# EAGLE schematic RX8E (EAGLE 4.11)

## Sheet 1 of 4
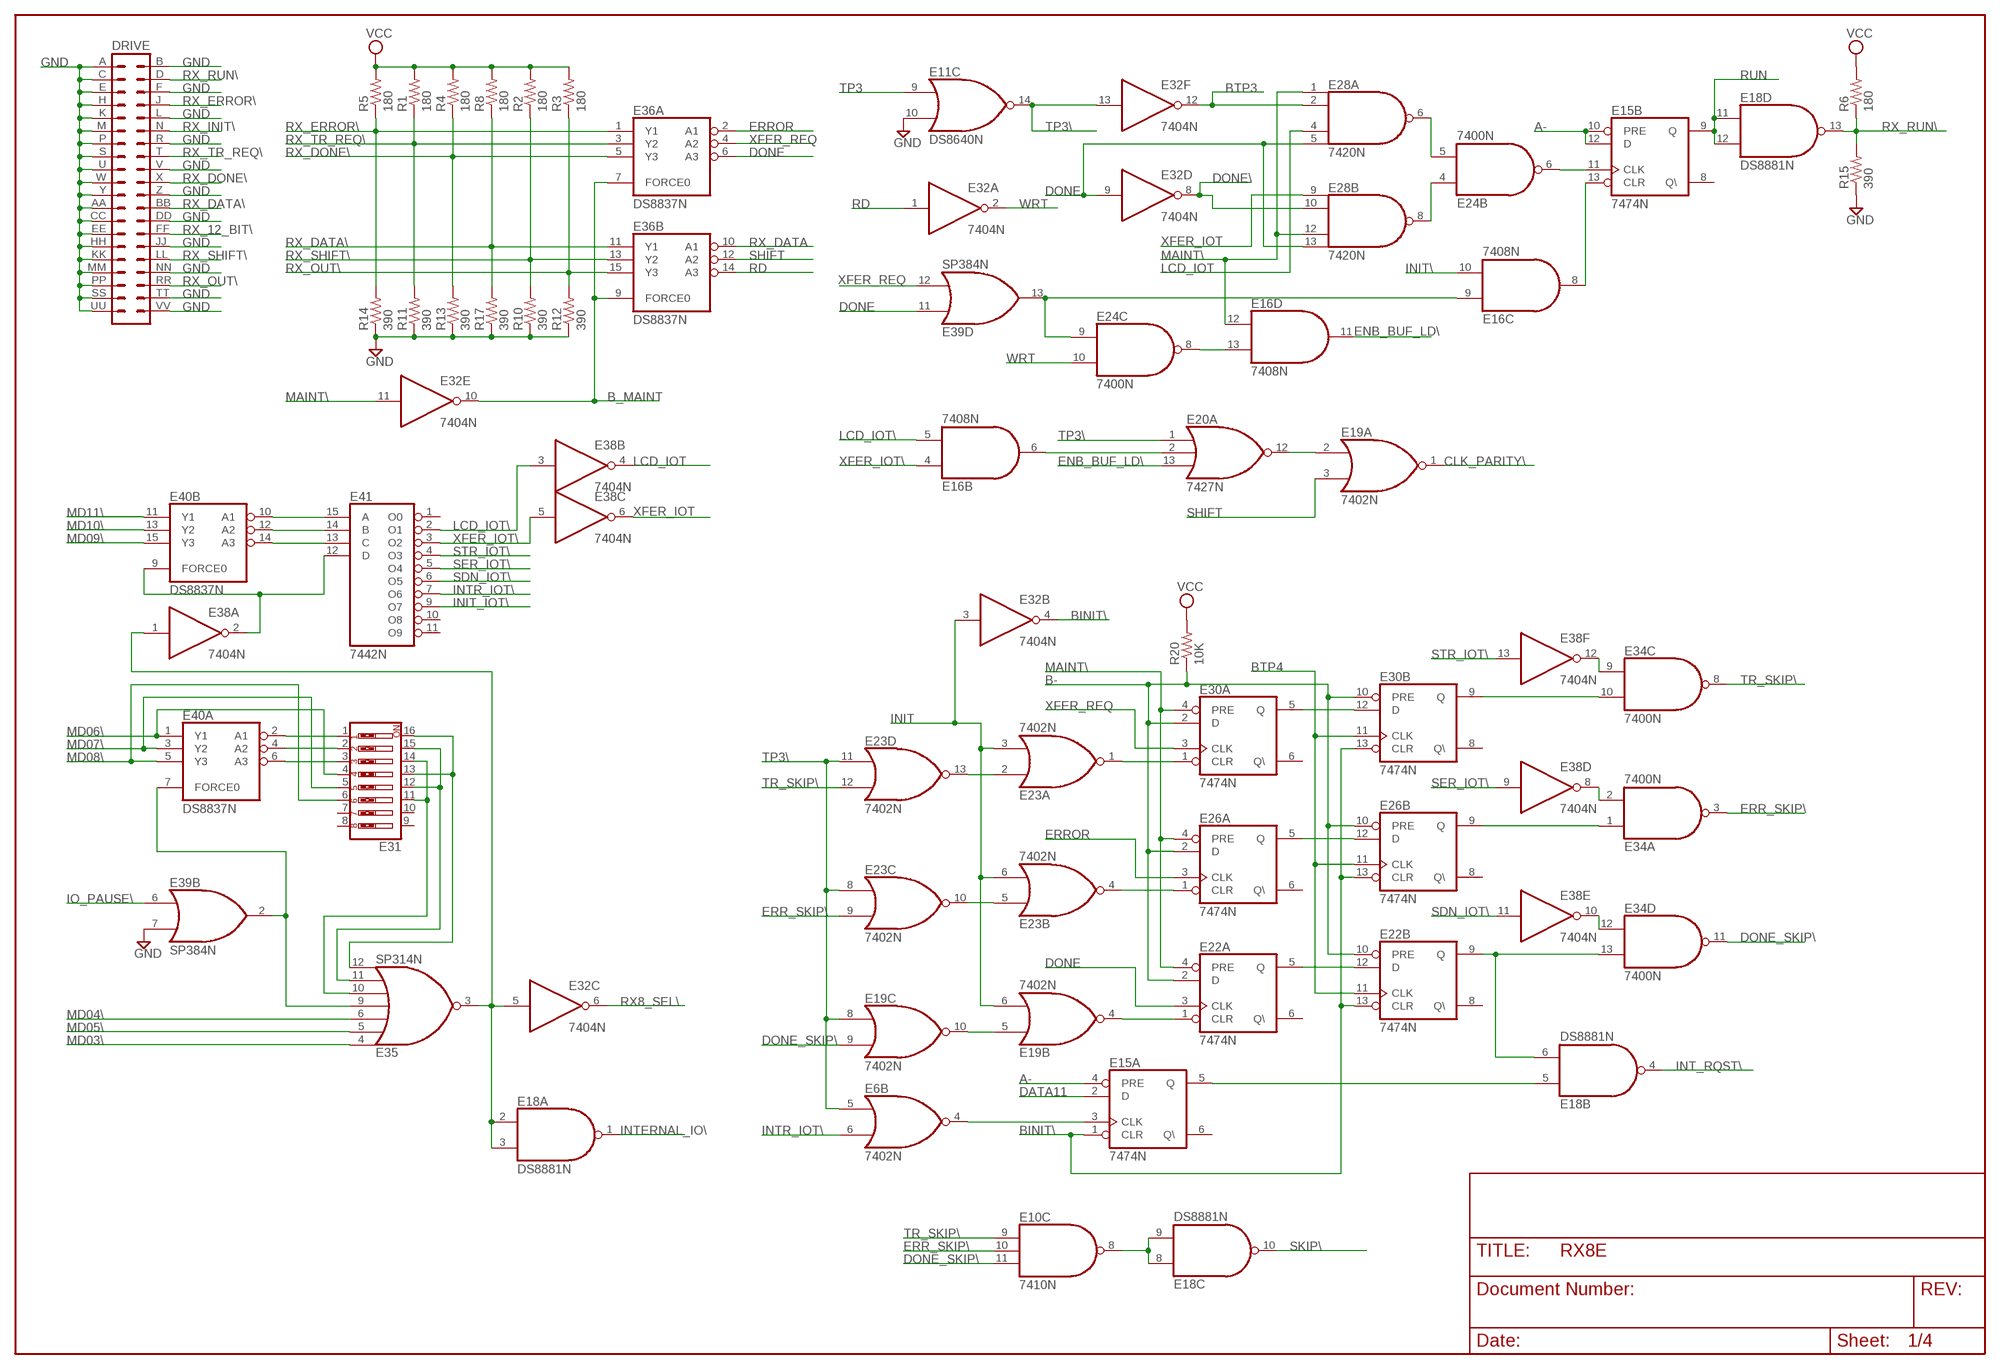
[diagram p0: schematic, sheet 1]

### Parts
DRIVE  DEC40PIN  [DEC40PIN]
E6  7402N  74LS02N  [DIL14]
E10  7410N  74LS10N  [DIL14]
E11  DS8640N  8640N  [DIL14]
E15  7474N  74LS74N  [DIL14]
E16  7408N  74LS08N  [DIL14]
E18  DS8881N  74LS01N  [DIL14]
E19  7402N  74LS02N  [DIL14]
E20  7427N  74LS27N  [DIL14]
E22  7474N  74LS74N  [DIL14]
E23  7402N  74LS02N  [DIL14]
E24  7400N  74LS00N  [DIL14]
E26  7474N  74LS74N  [DIL14]
E28  7420N  74LS20N  [DIL14]
E30  7474N  74LS74N  [DIL14]
E31  SW_DIP-8  [EDG-08]
E32  7404N  74LS04N  [DIL14]
E34  7400N  [DIL14]
E35  SP314N  [DIL14]
E36  DS8837N  8837N  [DIL16]
E38  7404N  74LS04N  [DIL14]
E39  SP384N  [DIL14]
E40  DS8837N  8837N  [DIL16]
E41  7442N  74LS42N  [DIL16]
R1  180  R-US_0207/10  [0207/10]
R2  180  R-US_0207/10  [0207/10]
R3  180  R-US_0207/10  [0207/10]
R4  180  R-US_0207/10  [0207/10]
R5  180  R-US_0207/10  [0207/10]
R6  180  R-US_0207/10  [0207/10]
R8  180  R-US_0207/10  [0207/10]
R10  390  R-US_0207/10  [0207/10]
R11  390  R-US_0207/10  [0207/10]
R12  390  R-US_0207/10  [0207/10]
R13  390  R-US_0207/10  [0207/10]
R14  390  R-US_0207/10  [0207/10]
R15  390  R-US_0207/10  [0207/10]
R17  390  R-US_0207/10  [0207/10]
R20  10K  R-US_0207/10  [0207/10]

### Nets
A-: E15.4(A:PRE) E15.10(B:PRE) E15.12(B:D) ; also sheet 2
B-: E22.2(A:D) E22.10(B:PRE) E26.2(A:D) E26.10(B:PRE) E30.2(A:D) E30.10(B:PRE) R20.1 ; also sheet 2
B_MAINT: E32.10(E:O) E36.7(A:FORCE0) E36.9(B:FORCE0)
BINIT\: E15.1(A:CLR) E22.13(B:CLR) E26.13(B:CLR) E30.13(B:CLR) E32.4(B:O)
BTP3: E28.2(A:I1) E32.12(F:O) ; also sheet 2
BTP4: E22.11(B:CLK) E26.11(B:CLK) E30.11(B:CLK) ; also sheet 2
CLK_PARITY\: E19.1(A:O) ; also sheet 2
DATA11: E15.2(A:D) ; also sheet 2
DONE: E22.3(A:CLK) E28.5(A:I3) E28.13(B:I3) E32.9(D:I) E36.6(A:A3) E39.11(D:I0) ; also sheet 2
DONE\: E28.10(B:I1) E32.8(D:O) ; also sheet 2
DONE_SKIP\: E10.11(C:I2) E19.9(C:I1) E34.11(D:O) ; also sheet 3
ENB_BUF_LD\: E16.11(D:O) E20.13(A:I2) ; also sheet 2
ERR_SKIP\: E10.10(C:I1) E23.9(C:I1) E34.3(A:O)
ERROR: E26.3(A:CLK) E36.2(A:A1)
GND [supply]: DRIVE.A DRIVE.AA DRIVE.B DRIVE.C DRIVE.CC DRIVE.DD DRIVE.E DRIVE.EE DRIVE.F DRIVE.H DRIVE.HH DRIVE.JJ DRIVE.K DRIVE.KK DRIVE.L DRIVE.M DRIVE.MM DRIVE.NN DRIVE.P DRIVE.PP DRIVE.R DRIVE.S DRIVE.SS DRIVE.TT DRIVE.U DRIVE.UU DRIVE.V DRIVE.VV DRIVE.W DRIVE.Y DRIVE.Z E11.10(C:I1) E39.7(B:I1) R10.1 R11.1 R12.1 R13.1 R14.1 R15.1 R17.1 ; also sheet 2,3
INIT: E19.6(B:I1) E23.3(A:I1) E23.6(B:I1) E32.3(B:I) ; also sheet 2
INIT\: E16.10(C:I1) ; also sheet 2
INIT_IOT\: E41.9(O7) ; also sheet 2
INT_RQST\: E18.4(B:O) ; also sheet 3
INTERNAL_IO\: E18.1(A:O) ; also sheet 3
INTR_IOT\: E6.6(B:I1) E41.7(O6)
IO_PAUSE\: E39.6(B:I0) ; also sheet 3
LCD_IOT: E28.4(A:I2) E38.4(B:O) ; also sheet 2
LCD_IOT\: E16.5(B:I1) E38.3(B:I) E41.2(O1) ; also sheet 2
MAINT\: E16.12(D:I0) E22.4(A:PRE) E26.4(A:PRE) E28.1(A:I0) E28.12(B:I2) E30.4(A:PRE) E32.11(E:I) ; also sheet 2
MD03\: E35.4(I0) ; also sheet 3
MD04\: E35.6(I2) ; also sheet 3
MD05\: E35.5(I1) ; also sheet 3
MD06\: E31.4 E40.1(A:Y1) ; also sheet 3
MD07\: E31.5 E40.3(A:Y2) ; also sheet 3
MD08\: E31.6 E40.5(A:Y3) ; also sheet 3
MD09\: E40.15(B:Y3) ; also sheet 3
MD10\: E40.13(B:Y2) ; also sheet 3
MD11\: E40.11(B:Y1) ; also sheet 3
N$1: E31.11 E31.14 E35.10(I4)
N$5: E31.12 E31.15 E35.11(I5)
N$6: E31.13 E31.16 E35.12(I6)
N$7: E31.3 E40.6(A:A3)
N$8: E31.2 E40.4(A:A2)
N$9: E31.1 E40.2(A:A1)
N$10: E35.9(I3) E39.2(B:O) E40.7(A:FORCE0)
N$11: E18.2(A:I0) E18.3(A:I1) E32.5(C:I) E35.3(O) E38.1(A:I)
N$49: E19.5(B:I0) E19.10(C:O)
N$50: E38.2(A:O) E40.9(B:FORCE0) E41.12(D)
N$51: E40.14(B:A3) E41.13(C)
N$52: E40.12(B:A2) E41.14(B)
N$53: E40.10(B:A1) E41.15(A)
N$54: E19.4(B:O) E22.1(A:CLR)
N$55: E23.4(B:O) E26.1(A:CLR)
N$56: E23.5(B:I0) E23.10(C:O)
N$57: E23.2(A:I0) E23.13(D:O)
N$58: E23.1(A:O) E30.1(A:CLR)
N$59: E30.5(A:Q) E30.12(B:D)
N$61: E26.5(A:Q) E26.12(B:D)
N$68: E22.5(A:Q) E22.12(B:D)
N$69: E18.6(B:I1) E22.9(B:Q) E34.13(D:I1)
N$70: E26.9(B:Q) E34.1(A:I0)
N$71: E6.4(B:O) E15.3(A:CLK)
N$72: E30.9(B:Q) E34.10(C:I1)
N$73: E34.2(A:I1) E38.8(D:O)
N$74: E34.12(D:I0) E38.10(E:O)
N$75: E34.9(C:I0) E38.12(F:O)
N$76: E15.5(A:Q) E18.5(B:I0)
N$77: E10.8(C:O) E18.8(C:I0) E18.9(C:I1)
N$78: E24.5(B:I1) E28.6(A:O)
N$79: E16.6(B:O) E20.2(A:I1)
N$80: E24.4(B:I0) E28.8(B:O)
N$81: E16.9(C:I0) E24.9(C:I0) E39.13(D:O)
N$82: E16.13(D:I1) E24.8(C:O)
N$83: E15.13(B:CLR) E16.8(C:O)
N$84: E19.2(A:I0) E20.12(A:O)
N$85: E15.11(B:CLK) E24.6(B:O)
RD: E32.1(A:I) E36.14(B:A3) ; also sheet 2
RUN: E15.9(B:Q) E18.11(D:I0) E18.12(D:I1) ; also sheet 2
RX8_SEL\: E32.6(C:O) ; also sheet 2
RX_12_BIT\: DRIVE.FF ; also sheet 2
RX_DATA: E36.10(B:A1) ; also sheet 2
RX_DATA\: DRIVE.BB E36.11(B:Y1) R8.1 R17.2 ; also sheet 2
RX_DONE\: DRIVE.X E36.5(A:Y3) R4.1 R13.2
RX_ERROR\: DRIVE.J E36.1(A:Y1) R5.1 R14.2
RX_INIT\: DRIVE.N ; also sheet 2
RX_OUT\: DRIVE.RR E36.15(B:Y3) R3.1 R12.2
RX_RUN\: DRIVE.D E18.13(D:O) R6.1 R15.2
RX_SHIFT\: DRIVE.LL E36.13(B:Y2) R2.1 R10.2
RX_TR_REQ\: DRIVE.T E36.3(A:Y2) R1.1 R11.2
SDN_IOT\: E38.11(E:I) E41.6(O5)
SER_IOT\: E38.9(D:I) E41.5(O4)
SHIFT: E19.3(A:I1) E36.12(B:A2)
SKIP\: E18.10(C:O) ; also sheet 3
STR_IOT\: E38.13(F:I) E41.4(O3)
TP3: E11.9(C:I0) ; also sheet 3
TP3\: E6.5(B:I0) E11.14(C:O) E19.8(C:I0) E20.1(A:I0) E23.8(C:I0) E23.11(D:I0) E32.13(F:I) ; also sheet 2
TR_SKIP\: E10.9(C:I0) E23.12(D:I1) E34.8(C:O) ; also sheet 3
VCC [supply]: R1.2 R2.2 R3.2 R4.2 R5.2 R6.2 R8.2 R20.2 ; also sheet 2,3
WRT: E24.10(C:I1) E32.2(A:O) ; also sheet 2
XFER_IOT: E28.9(B:I0) E38.6(C:O) ; also sheet 2
XFER_IOT\: E16.4(B:I0) E38.5(C:I) E41.3(O2) ; also sheet 2
XFER_REQ: E30.3(A:CLK) E36.4(A:A2) E39.12(D:I1)
Unconnected: E6.8(C:I0) E6.9(C:I1) E6.10(C:O) E11.11(D:I0) E11.12(D:I1) E11.13(D:O) E15.6(A:Q\) E15.8(B:Q\) E20.3(B:I0) E20.4(B:I1) E20.5(B:I2) E20.6(B:O) E22.6(A:Q\) E22.8(B:Q\) E26.6(A:Q\) E26.8(B:Q\) E30.6(A:Q\) E30.8(B:Q\) E31.7 E31.8 E31.9 E31.10 E34.4(B:I0) E34.5(B:I1) E34.6(B:O) E39.3(A:O) E39.4(A:I0) E39.5(A:I1) E39.9(C:I0) E39.10(C:I1) E39.14(C:O) E41.1(O0) E41.10(O8) E41.11(O9)

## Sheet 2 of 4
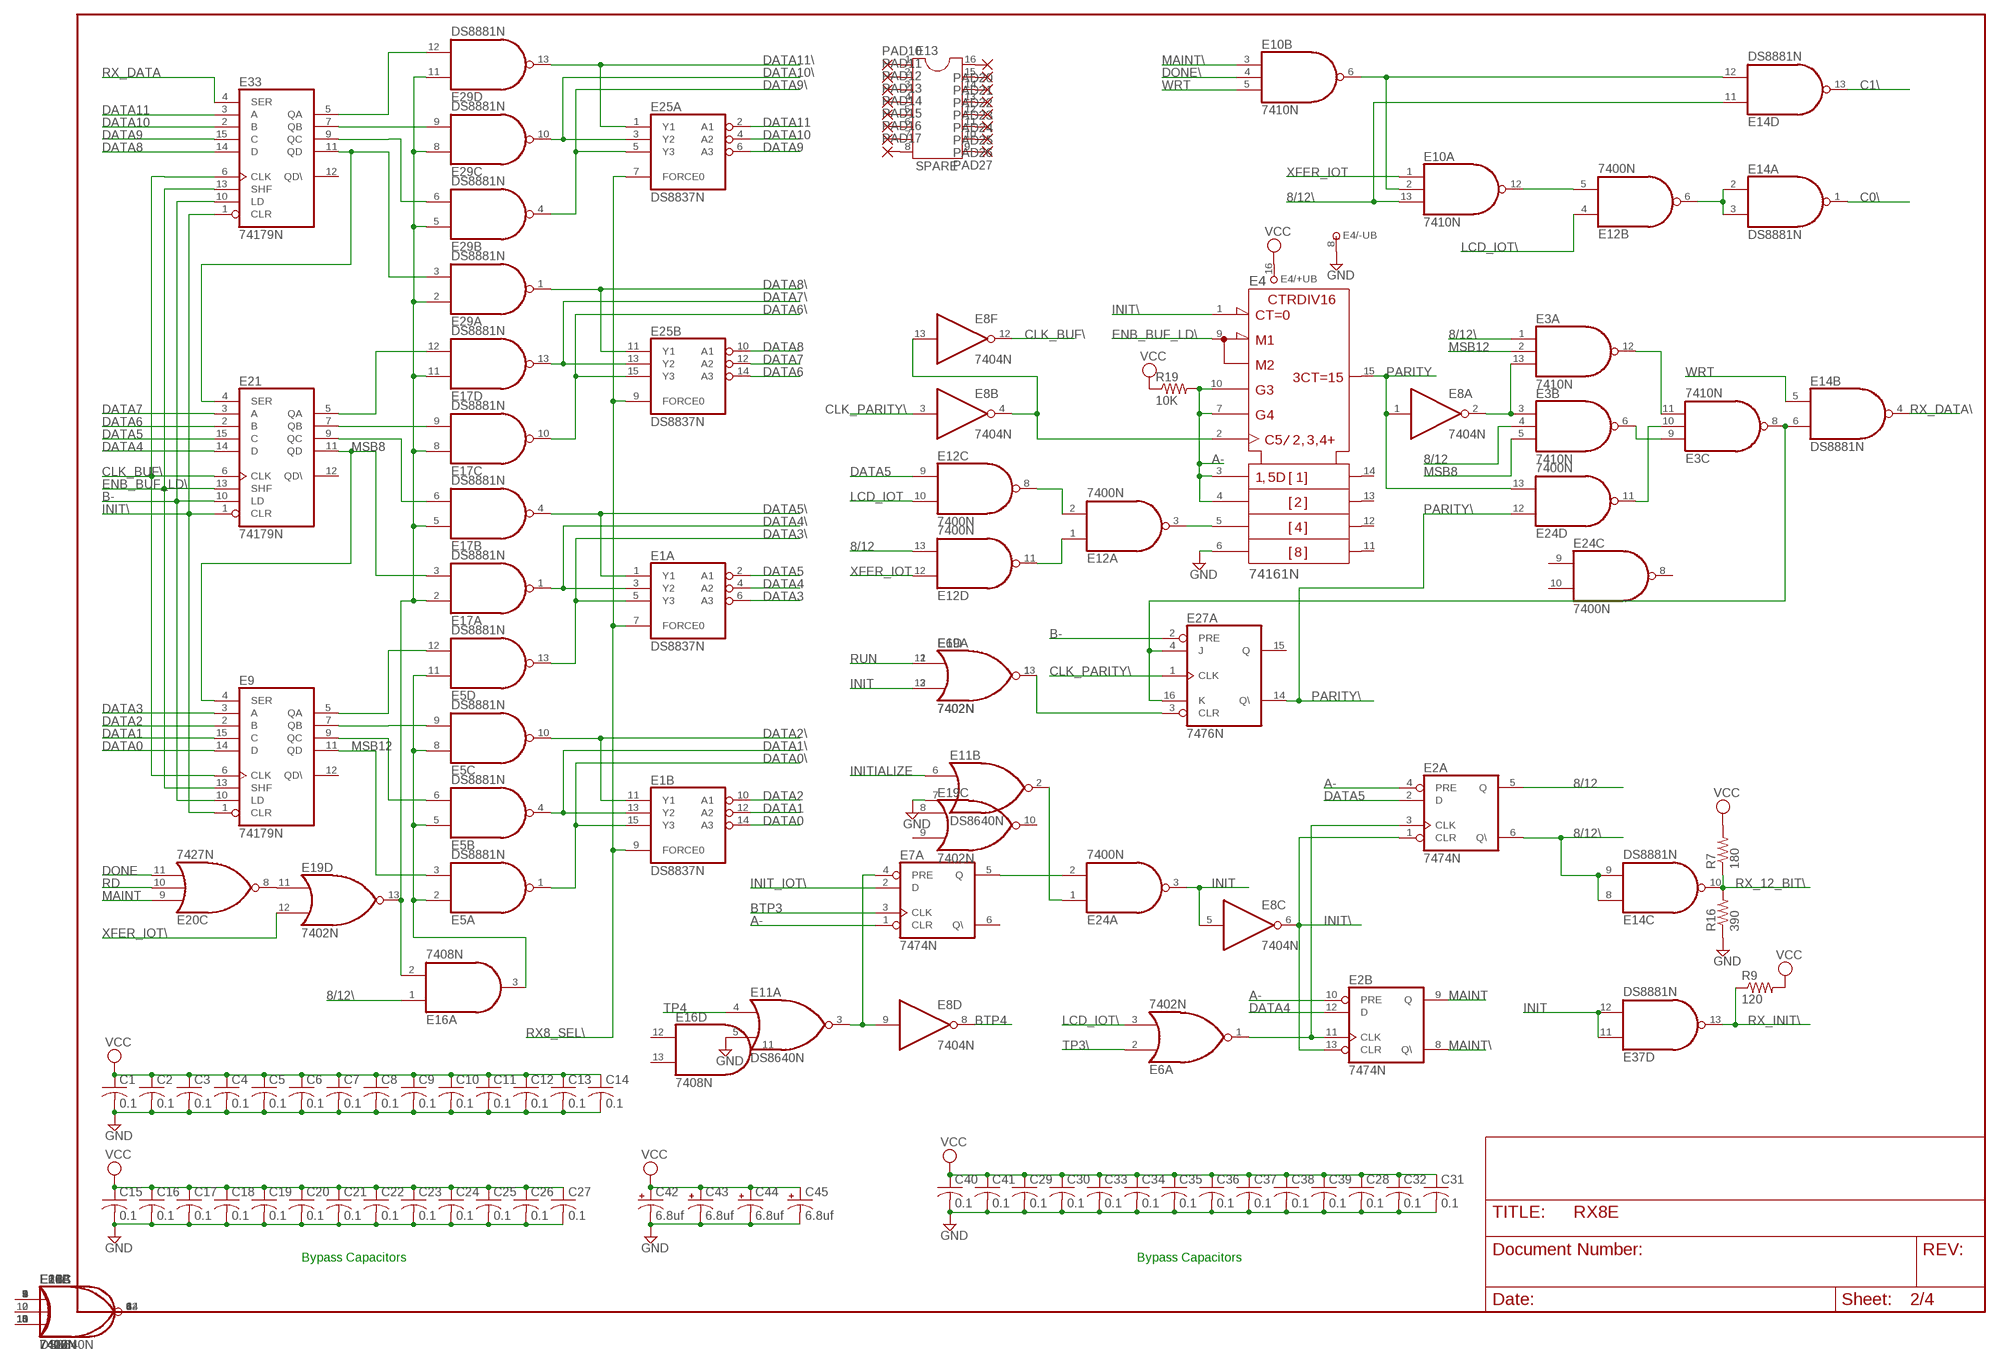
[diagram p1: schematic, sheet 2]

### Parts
C1  0.1  C-US050-025X075  [C050-025X075]
C2  0.1  C-US050-025X075  [C050-025X075]
C3  0.1  C-US050-025X075  [C050-025X075]
C4  0.1  C-US050-025X075  [C050-025X075]
C5  0.1  C-US050-025X075  [C050-025X075]
C6  0.1  C-US050-025X075  [C050-025X075]
C7  0.1  C-US050-025X075  [C050-025X075]
C8  0.1  C-US050-025X075  [C050-025X075]
C9  0.1  C-US050-025X075  [C050-025X075]
C10  0.1  C-US050-025X075  [C050-025X075]
C11  0.1  C-US050-025X075  [C050-025X075]
C12  0.1  C-US050-025X075  [C050-025X075]
C13  0.1  C-US050-025X075  [C050-025X075]
C14  0.1  C-US050-025X075  [C050-025X075]
C15  0.1  C-US050-025X075  [C050-025X075]
C16  0.1  C-US050-025X075  [C050-025X075]
C17  0.1  C-US050-025X075  [C050-025X075]
C18  0.1  C-US050-025X075  [C050-025X075]
C19  0.1  C-US050-025X075  [C050-025X075]
C20  0.1  C-US050-025X075  [C050-025X075]
C21  0.1  C-US050-025X075  [C050-025X075]
C22  0.1  C-US050-025X075  [C050-025X075]
C23  0.1  C-US050-025X075  [C050-025X075]
C24  0.1  C-US050-025X075  [C050-025X075]
C25  0.1  C-US050-025X075  [C050-025X075]
C26  0.1  C-US050-025X075  [C050-025X075]
C27  0.1  C-US050-025X075  [C050-025X075]
C28  0.1  C-US050-025X075  [C050-025X075]
C29  0.1  C-US050-025X075  [C050-025X075]
C30  0.1  C-US050-025X075  [C050-025X075]
C31  0.1  C-US050-025X075  [C050-025X075]
C32  0.1  C-US050-025X075  [C050-025X075]
C33  0.1  C-US050-025X075  [C050-025X075]
C34  0.1  C-US050-025X075  [C050-025X075]
C35  0.1  C-US050-025X075  [C050-025X075]
C36  0.1  C-US050-025X075  [C050-025X075]
C37  0.1  C-US050-025X075  [C050-025X075]
C38  0.1  C-US050-025X075  [C050-025X075]
C39  0.1  C-US050-025X075  [C050-025X075]
C40  0.1  C-US050-025X075  [C050-025X075]
C41  0.1  C-US050-025X075  [C050-025X075]
C42  6.8uf  CPOL-USE22-6AXIAL  [E22-6]
C43  6.8uf  CPOL-USE22-6AXIAL  [E22-6]
C44  6.8uf  CPOL-USE22-6AXIAL  [E22-6]
C45  6.8uf  CPOL-USE22-6AXIAL  [E22-6]
E1  DS8837N  8837N  [DIL16]
E2  7474N  74LS74N  [DIL14]
E3  7410N  74LS10N  [DIL14]
E4  74161N  [DIL16]
E5  DS8881N  74LS01N  [DIL14]
E7  7474N  74LS74N  [DIL14]
E8  7404N  74LS04N  [DIL14]
E9  74179N  [DIL16]
E12  7400N  74LS00N  [DIL14]
E13  SPARE  DIL16  [DIL16]
E14  DS8881N  74LS01N  [DIL14]
E17  DS8881N  74LS01N  [DIL14]
E21  74179N  [DIL16]
E25  DS8837N  8837N  [DIL16]
E27  7476N  [DIL16]
E29  DS8881N  74LS01N  [DIL14]
E33  74179N  [DIL16]
E37  DS8881N  74LS01N  [DIL14]
PAD10  1,6/0,8  [1,6/0,8]
PAD11  1,6/0,8  [1,6/0,8]
PAD12  1,6/0,8  [1,6/0,8]
PAD13  1,6/0,8  [1,6/0,8]
PAD14  1,6/0,8  [1,6/0,8]
PAD15  1,6/0,8  [1,6/0,8]
PAD16  1,6/0,8  [1,6/0,8]
PAD17  1,6/0,8  [1,6/0,8]
PAD20  1,6/0,8  [1,6/0,8]
PAD21  1,6/0,8  [1,6/0,8]
PAD22  1,6/0,8  [1,6/0,8]
PAD23  1,6/0,8  [1,6/0,8]
PAD24  1,6/0,8  [1,6/0,8]
PAD25  1,6/0,8  [1,6/0,8]
PAD26  1,6/0,8  [1,6/0,8]
PAD27  1,6/0,8  [1,6/0,8]
R7  180  R-US_0207/10  [0207/10]
R9  120  R-US_0207/10  [0207/10]
R16  390  R-US_0207/10  [0207/10]
R19  10K  R-US_0207/10  [0207/10]

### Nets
8/12: E2.5(A:Q) E3.4(B:I1) E12.13(D:I1)
8/12\: E2.6(A:Q\) E3.1(A:I0) E10.13(A:I2) E14.8(C:I0) E14.9(C:I1) E14.11(D:I0) E16.1(A:I0)
A-: E2.4(A:PRE) E2.10(B:PRE) E4.3(A) E4.4(B) E4.7(ENP) E4.10(ENT) E7.1(A:CLR) R19.2 ; also sheet 1
B-: E9.10(LD) E21.10(LD) E27.2(A:PRE) E33.10(LD) ; also sheet 1
BTP3: E7.3(A:CLK) ; also sheet 1
BTP4: E8.8(D:O) ; also sheet 1
C0\: E14.1(A:O) ; also sheet 3
C1\: E14.13(D:O) ; also sheet 3
CLK_BUF\: E8.12(F:O) E9.6(CLK) E21.6(CLK) E33.6(CLK)
CLK_PARITY\: E8.3(B:I) E27.1(A:CLK) ; also sheet 1
DATA0: E1.14(B:A3) E9.14(D)
DATA0\: E1.15(B:Y3) E5.1(A:O) ; also sheet 3
DATA1: E1.12(B:A2) E9.15(C)
DATA1\: E1.13(B:Y2) E5.4(B:O) ; also sheet 3
DATA2: E1.10(B:A1) E9.2(B)
DATA2\: E1.11(B:Y1) E5.10(C:O) ; also sheet 3
DATA3: E1.6(A:A3) E9.3(A)
DATA3\: E1.5(A:Y3) E5.13(D:O) ; also sheet 3
DATA4: E1.4(A:A2) E2.12(B:D) E21.14(D)
DATA4\: E1.3(A:Y2) E17.1(A:O) ; also sheet 3
DATA5: E1.2(A:A1) E2.2(A:D) E12.9(C:I0) E21.15(C)
DATA5\: E1.1(A:Y1) E17.4(B:O) ; also sheet 3
DATA6: E21.2(B) E25.14(B:A3)
DATA6\: E17.10(C:O) E25.15(B:Y3) ; also sheet 3
DATA7: E21.3(A) E25.12(B:A2)
DATA7\: E17.13(D:O) E25.13(B:Y2) ; also sheet 3
DATA8: E25.10(B:A1) E33.14(D)
DATA8\: E25.11(B:Y1) E29.1(A:O) ; also sheet 3
DATA9: E25.6(A:A3) E33.15(C)
DATA9\: E25.5(A:Y3) E29.4(B:O) ; also sheet 3
DATA10: E25.4(A:A2) E33.2(B)
DATA10\: E25.3(A:Y2) E29.10(C:O) ; also sheet 3
DATA11: E25.2(A:A1) E33.3(A) ; also sheet 1
DATA11\: E25.1(A:Y1) E29.13(D:O) ; also sheet 3
DONE: E20.11(C:I2) ; also sheet 1
DONE\: E10.4(B:I1) ; also sheet 1
ENB_BUF_LD\: E4.9(LOAD\) E9.13(SHF) E21.13(SHF) E33.13(SHF) ; also sheet 1
GND [supply]: C1.2 C2.2 C3.2 C4.2 C5.2 C6.2 C7.2 C8.2 C9.2 C10.2 C11.2 C12.2 C13.2 C14.2 C15.2 C16.2 C17.2 C18.2 C19.2 C20.2 C21.2 C22.2 C23.2 C24.2 C25.2 C26.2 C27.2 C28.2 C29.2 C30.2 C31.2 C32.2 C33.2 C34.2 C35.2 C36.2 C37.2 C38.2 C39.2 C40.2 C41.2 C42.- C43.- C44.- C45.- E4.6(D) E4.8(-UB) E11.5(A:I1) E11.7(B:I1) R16.1 ; also sheet 1,3
INIT: E6.12(D:I1) E8.5(C:I) E24.3(A:O) E37.11(D:I0) E37.12(D:I1) ; also sheet 1
INIT\: E2.1(A:CLR) E2.13(B:CLR) E4.1(CLR\) E8.6(C:O) E9.1(CLR) E21.1(CLR) E33.1(CLR) ; also sheet 1
INIT_IOT\: E7.2(A:D) ; also sheet 1
INITIALIZE: E11.6(B:I0) ; also sheet 3
LCD_IOT: E12.10(C:I1) ; also sheet 1
LCD_IOT\: E6.3(A:I1) E12.4(B:I0) ; also sheet 1
MAINT: E2.9(B:Q) E20.9(C:I0)
MAINT\: E2.8(B:Q\) E10.3(B:I0) ; also sheet 1
MSB8: E3.5(B:I2) E9.4(SER) E17.3(A:I1) E21.11(QD)
MSB12: E3.2(A:I1) E5.3(A:I1) E9.11(QD)
N$2: E5.9(C:I1) E9.7(QB)
N$3: E16.2(A:I1) E17.2(A:I0) E17.5(B:I0) E17.8(C:I0) E17.11(D:I0) E19.13(D:O) E29.2(A:I0) E29.5(B:I0) E29.8(C:I0) E29.11(D:I0)
N$4: E19.11(D:I0) E20.8(C:O)
N$12: E5.2(A:I0) E5.5(B:I0) E5.8(C:I0) E5.11(D:I0) E16.3(A:O)
N$13: E13.1 PAD10.1(P)
N$14: E13.2 PAD11.1(P)
N$15: E13.3 PAD12.1(P)
N$16: E13.4 PAD13.1(P)
N$17: E13.5 PAD14.1(P)
N$18: E13.6 PAD15.1(P)
N$19: E13.7 PAD16.1(P)
N$20: E13.8 PAD17.1(P)
N$21: E4.5(C) E12.3(A:O)
N$22: E12.6(B:O) E14.2(A:I0) E14.3(A:I1)
N$23: E13.16 PAD20.1(P)
N$24: E13.15 PAD21.1(P)
N$25: E13.14 PAD22.1(P)
N$26: E13.13 PAD23.1(P)
N$27: E13.12 PAD24.1(P)
N$28: E13.11 PAD25.1(P)
N$29: E13.10 PAD26.1(P)
N$30: E13.9 PAD27.1(P)
N$31: E21.4(SER) E29.3(A:I1) E33.11(QD)
N$32: E10.12(A:O) E12.5(B:I1)
N$33: E5.6(B:I1) E9.9(QC)
N$34: E10.2(A:I1) E10.6(B:O) E14.12(D:I1)
N$35: E12.1(A:I0) E12.11(D:O)
N$36: E12.2(A:I1) E12.8(C:O)
N$37: E3.3(B:I0) E3.13(A:I2) E8.2(A:O)
N$38: E3.11(C:I2) E3.12(A:O)
N$39: E3.6(B:O) E3.9(C:I0)
N$40: E3.10(C:I1) E24.11(D:O)
N$42: E3.8(C:O) E14.6(B:I1) E27.4(A:J) E27.16(A:K)
N$43: E7.4(A:PRE) E8.9(D:I) E11.3(A:O)
N$44: E4.2(CLK) E8.4(B:O) E8.13(F:I)
N$45: E7.5(A:Q) E24.2(A:I1)
N$46: E6.13(D:O) E27.3(A:CLR)
N$47: E11.2(B:O) E24.1(A:I0)
N$48: E2.3(A:CLK) E2.11(B:CLK) E6.1(A:O)
N$60: E5.12(D:I1) E9.5(QA)
N$62: E17.6(B:I1) E21.9(QC)
N$63: E17.9(C:I1) E21.7(QB)
N$64: E17.12(D:I1) E21.5(QA)
N$65: E29.12(D:I1) E33.5(QA)
N$66: E29.6(B:I1) E33.9(QC)
N$67: E29.9(C:I1) E33.7(QB)
PARITY: E4.15(RCO) E8.1(A:I) E24.13(D:I1) ; also sheet 3
PARITY\: E24.12(D:I0) E27.14(A:Q\)
RD: E20.10(C:I1) ; also sheet 1
RUN: E6.11(D:I0) ; also sheet 1
RX8_SEL\: E1.7(A:FORCE0) E1.9(B:FORCE0) E25.7(A:FORCE0) E25.9(B:FORCE0) ; also sheet 1
RX_12_BIT\: E14.10(C:O) R7.1 R16.2 ; also sheet 1
RX_DATA: E33.4(SER) ; also sheet 1
RX_DATA\: E14.4(B:O) ; also sheet 1
RX_INIT\: E37.13(D:O) R9.1 ; also sheet 1
TP3\: E6.2(A:I0) ; also sheet 1
TP4: E11.4(A:I0) ; also sheet 3
VCC [supply]: C1.1 C2.1 C3.1 C4.1 C5.1 C6.1 C7.1 C8.1 C9.1 C10.1 C11.1 C12.1 C13.1 C14.1 C15.1 C16.1 C17.1 C18.1 C19.1 C20.1 C21.1 C22.1 C23.1 C24.1 C25.1 C26.1 C27.1 C28.1 C29.1 C30.1 C31.1 C32.1 C33.1 C34.1 C35.1 C36.1 C37.1 C38.1 C39.1 C40.1 C41.1 C42.+ C43.+ C44.+ C45.+ E4.16(+UB) R7.2 R9.2 R19.1 ; also sheet 1,3
WRT: E10.5(B:I2) E14.5(B:I0) ; also sheet 1
XFER_IOT: E10.1(A:I0) E12.12(D:I0) ; also sheet 1
XFER_IOT\: E19.12(D:I1) ; also sheet 1
Unconnected: E4.11(QD) E4.12(QC) E4.13(QB) E4.14(QA) E7.6(A:Q\) E7.8(B:Q\) E7.9(B:Q) E7.10(B:PRE) E7.11(B:CLK) E7.12(B:D) E7.13(B:CLR) E8.10(E:O) E8.11(E:I) E9.12(QD\) E21.12(QD\) E27.6(B:CLK) E27.7(B:PRE) E27.8(B:CLR) E27.9(B:J) E27.10(B:Q\) E27.11(B:Q) E27.12(B:K) E27.15(A:Q) E33.12(QD\) E37.1(A:O) E37.2(A:I0) E37.3(A:I1) E37.4(B:O) E37.5(B:I0) E37.6(B:I1) E37.8(C:I0) E37.9(C:I1) E37.10(C:O)

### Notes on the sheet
- Bypass Capacitors | Bypass Capacitors

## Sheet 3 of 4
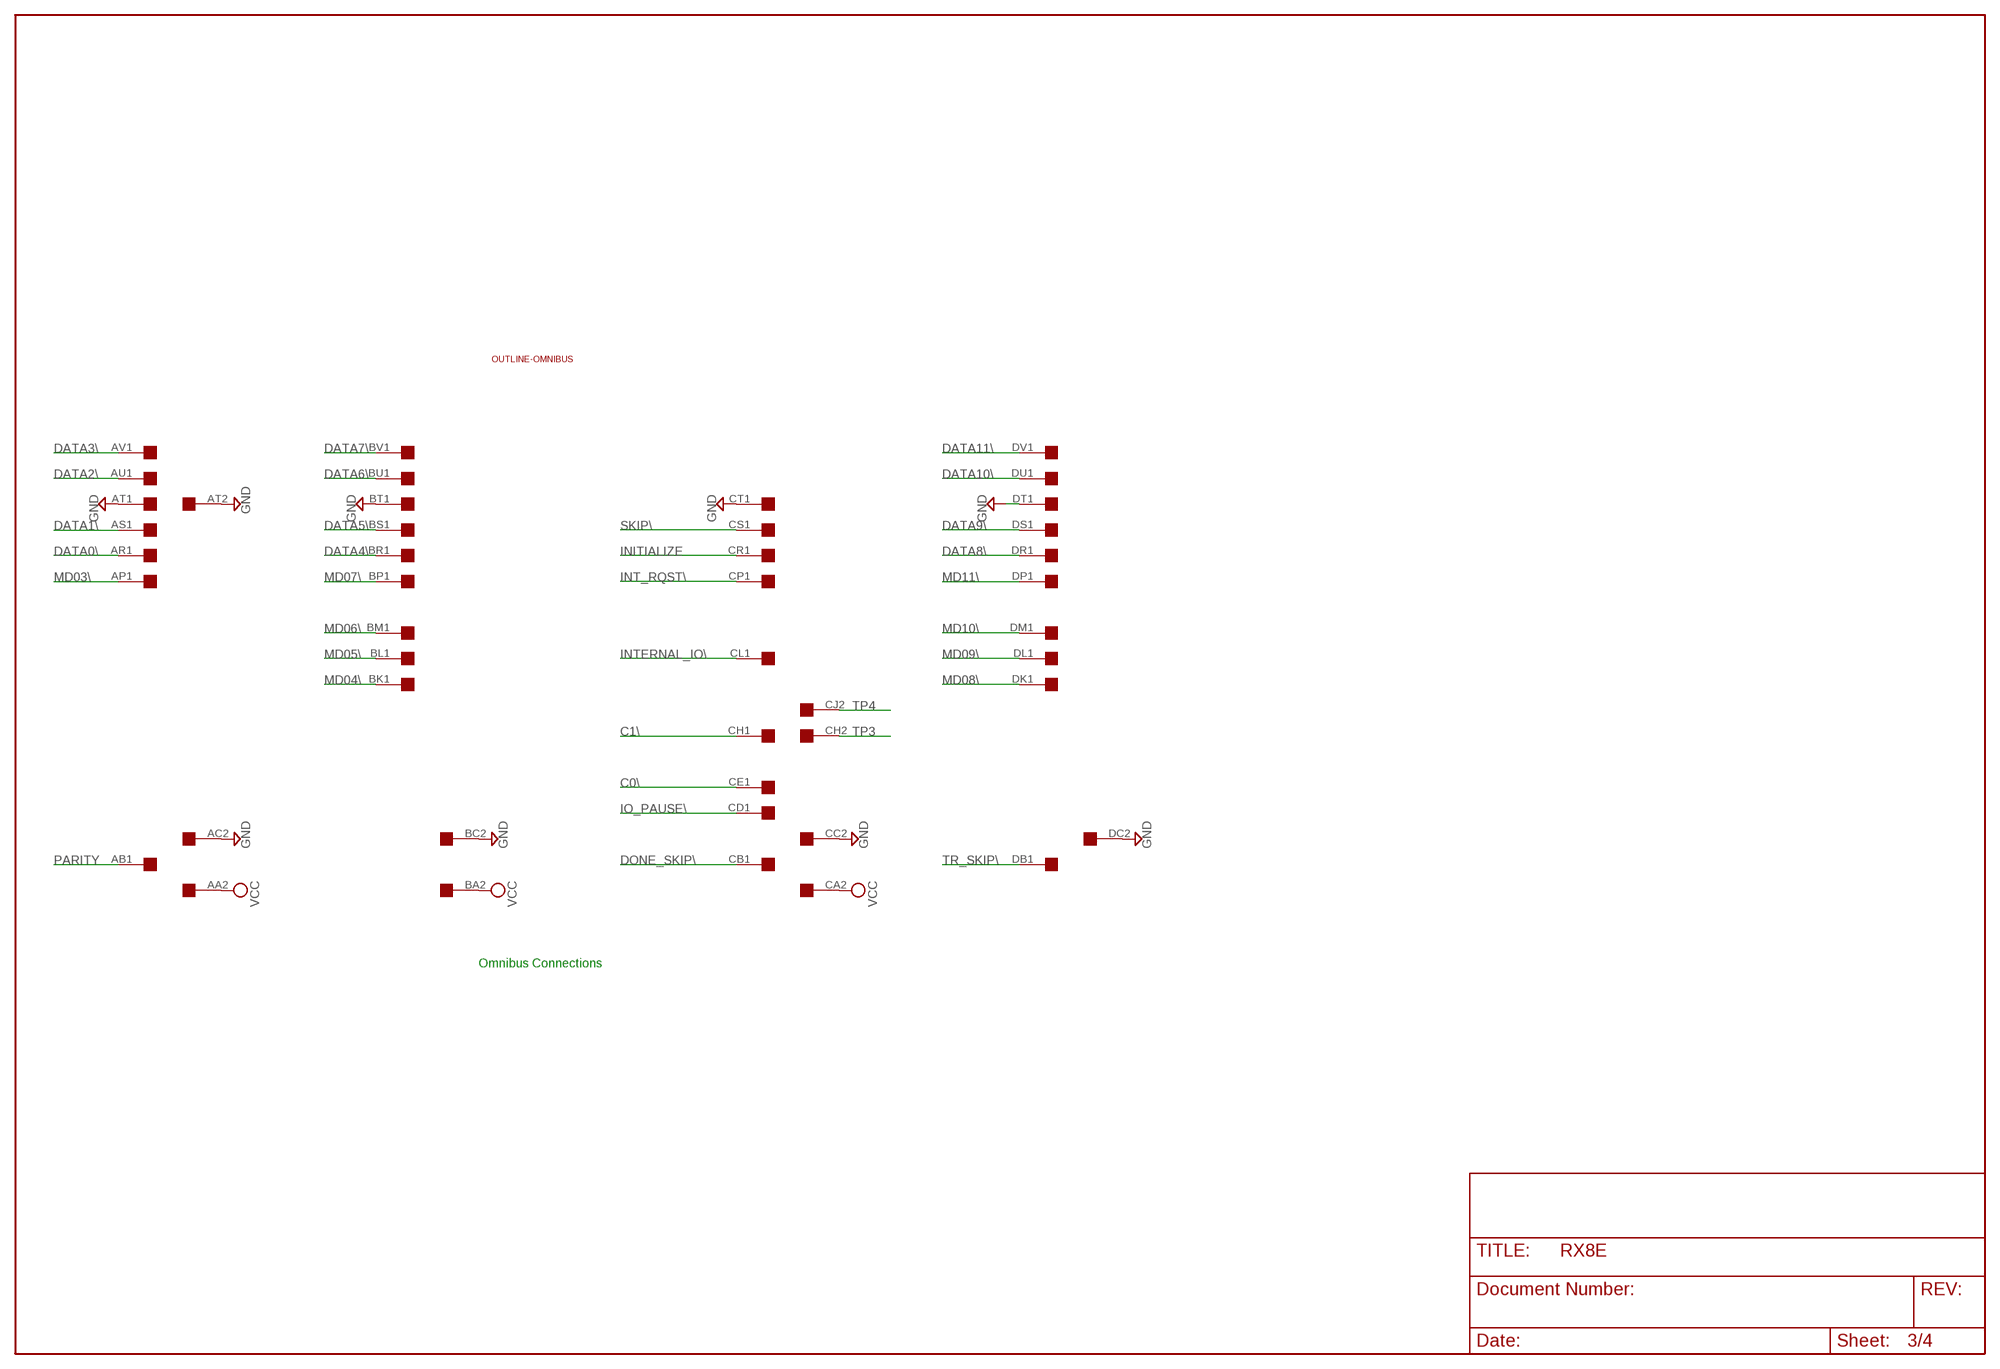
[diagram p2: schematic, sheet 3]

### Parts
U$2  QUAD  [EDGE-CON8]
U$5  OUTLINE-OMNIBUS  [OMNIBUS]

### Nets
C0\: U$2.CE1 ; also sheet 2
C1\: U$2.CH1 ; also sheet 2
DATA0\: U$2.AR1 ; also sheet 2
DATA1\: U$2.AS1 ; also sheet 2
DATA2\: U$2.AU1 ; also sheet 2
DATA3\: U$2.AV1 ; also sheet 2
DATA4\: U$2.BR1 ; also sheet 2
DATA5\: U$2.BS1 ; also sheet 2
DATA6\: U$2.BU1 ; also sheet 2
DATA7\: U$2.BV1 ; also sheet 2
DATA8\: U$2.DR1 ; also sheet 2
DATA9\: U$2.DS1 ; also sheet 2
DATA10\: U$2.DU1 ; also sheet 2
DATA11\: U$2.DV1 ; also sheet 2
DONE_SKIP\: U$2.CB1 ; also sheet 1
GND [supply]: U$2.AC2 U$2.AT1 U$2.AT2 U$2.BC2 U$2.BT1 U$2.CC2 U$2.CT1 U$2.DC2 U$2.DT1 ; also sheet 1,2
INITIALIZE: U$2.CR1 ; also sheet 2
INT_RQST\: U$2.CP1 ; also sheet 1
INTERNAL_IO\: U$2.CL1 ; also sheet 1
IO_PAUSE\: U$2.CD1 ; also sheet 1
MD03\: U$2.AP1 ; also sheet 1
MD04\: U$2.BK1 ; also sheet 1
MD05\: U$2.BL1 ; also sheet 1
MD06\: U$2.BM1 ; also sheet 1
MD07\: U$2.BP1 ; also sheet 1
MD08\: U$2.DK1 ; also sheet 1
MD09\: U$2.DL1 ; also sheet 1
MD10\: U$2.DM1 ; also sheet 1
MD11\: U$2.DP1 ; also sheet 1
PARITY: U$2.AB1 ; also sheet 2
SKIP\: U$2.CS1 ; also sheet 1
TP3: U$2.CH2 ; also sheet 1
TP4: U$2.CJ2 ; also sheet 2
TR_SKIP\: U$2.DB1 ; also sheet 1
VCC [supply]: U$2.AA2 U$2.BA2 U$2.CA2 ; also sheet 1,2
Unconnected: U$2.AA1 U$2.AB2 U$2.AC1 U$2.AD1 U$2.AD2 U$2.AE1 U$2.AE2 U$2.AF1 U$2.AF2 U$2.AH1 U$2.AH2 U$2.AJ1 U$2.AJ2 U$2.AK1 U$2.AK2 U$2.AL1 U$2.AL2 U$2.AM1 U$2.AM2 U$2.AN1 U$2.AN2 U$2.AP2 U$2.AR2 U$2.AS2 U$2.AU2 U$2.AV2 U$2.BA1 U$2.BB1 U$2.BB2 U$2.BC1 U$2.BD1 U$2.BD2 U$2.BE1 U$2.BE2 U$2.BF1 U$2.BF2 U$2.BH1 U$2.BH2 U$2.BJ1 U$2.BJ2 U$2.BK2 U$2.BL2 U$2.BM2 U$2.BN1 U$2.BN2 U$2.BP2 U$2.BR2 U$2.BS2 U$2.BT2 U$2.BU2 U$2.BV2 U$2.CA1 U$2.CB2 U$2.CC1 U$2.CD2 U$2.CE2 U$2.CF1 U$2.CF2 U$2.CJ1 U$2.CK1 U$2.CK2 U$2.CL2 U$2.CM1 U$2.CM2 U$2.CN1 U$2.CN2 U$2.CP2 U$2.CR2 U$2.CS2 U$2.CT2 U$2.CU1 U$2.CU2 U$2.CV1 U$2.CV2 U$2.DA1 U$2.DA2 U$2.DB2 U$2.DC1 U$2.DD1 U$2.DD2 U$2.DE1 U$2.DE2 U$2.DF1 U$2.DF2 U$2.DH1 U$2.DH2 U$2.DJ1 U$2.DJ2 U$2.DK2 U$2.DL2 U$2.DM2 U$2.DN1 U$2.DN2 U$2.DP2 U$2.DR2 U$2.DS2 U$2.DT2 U$2.DU2 U$2.DV2

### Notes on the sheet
- Omnibus Connections

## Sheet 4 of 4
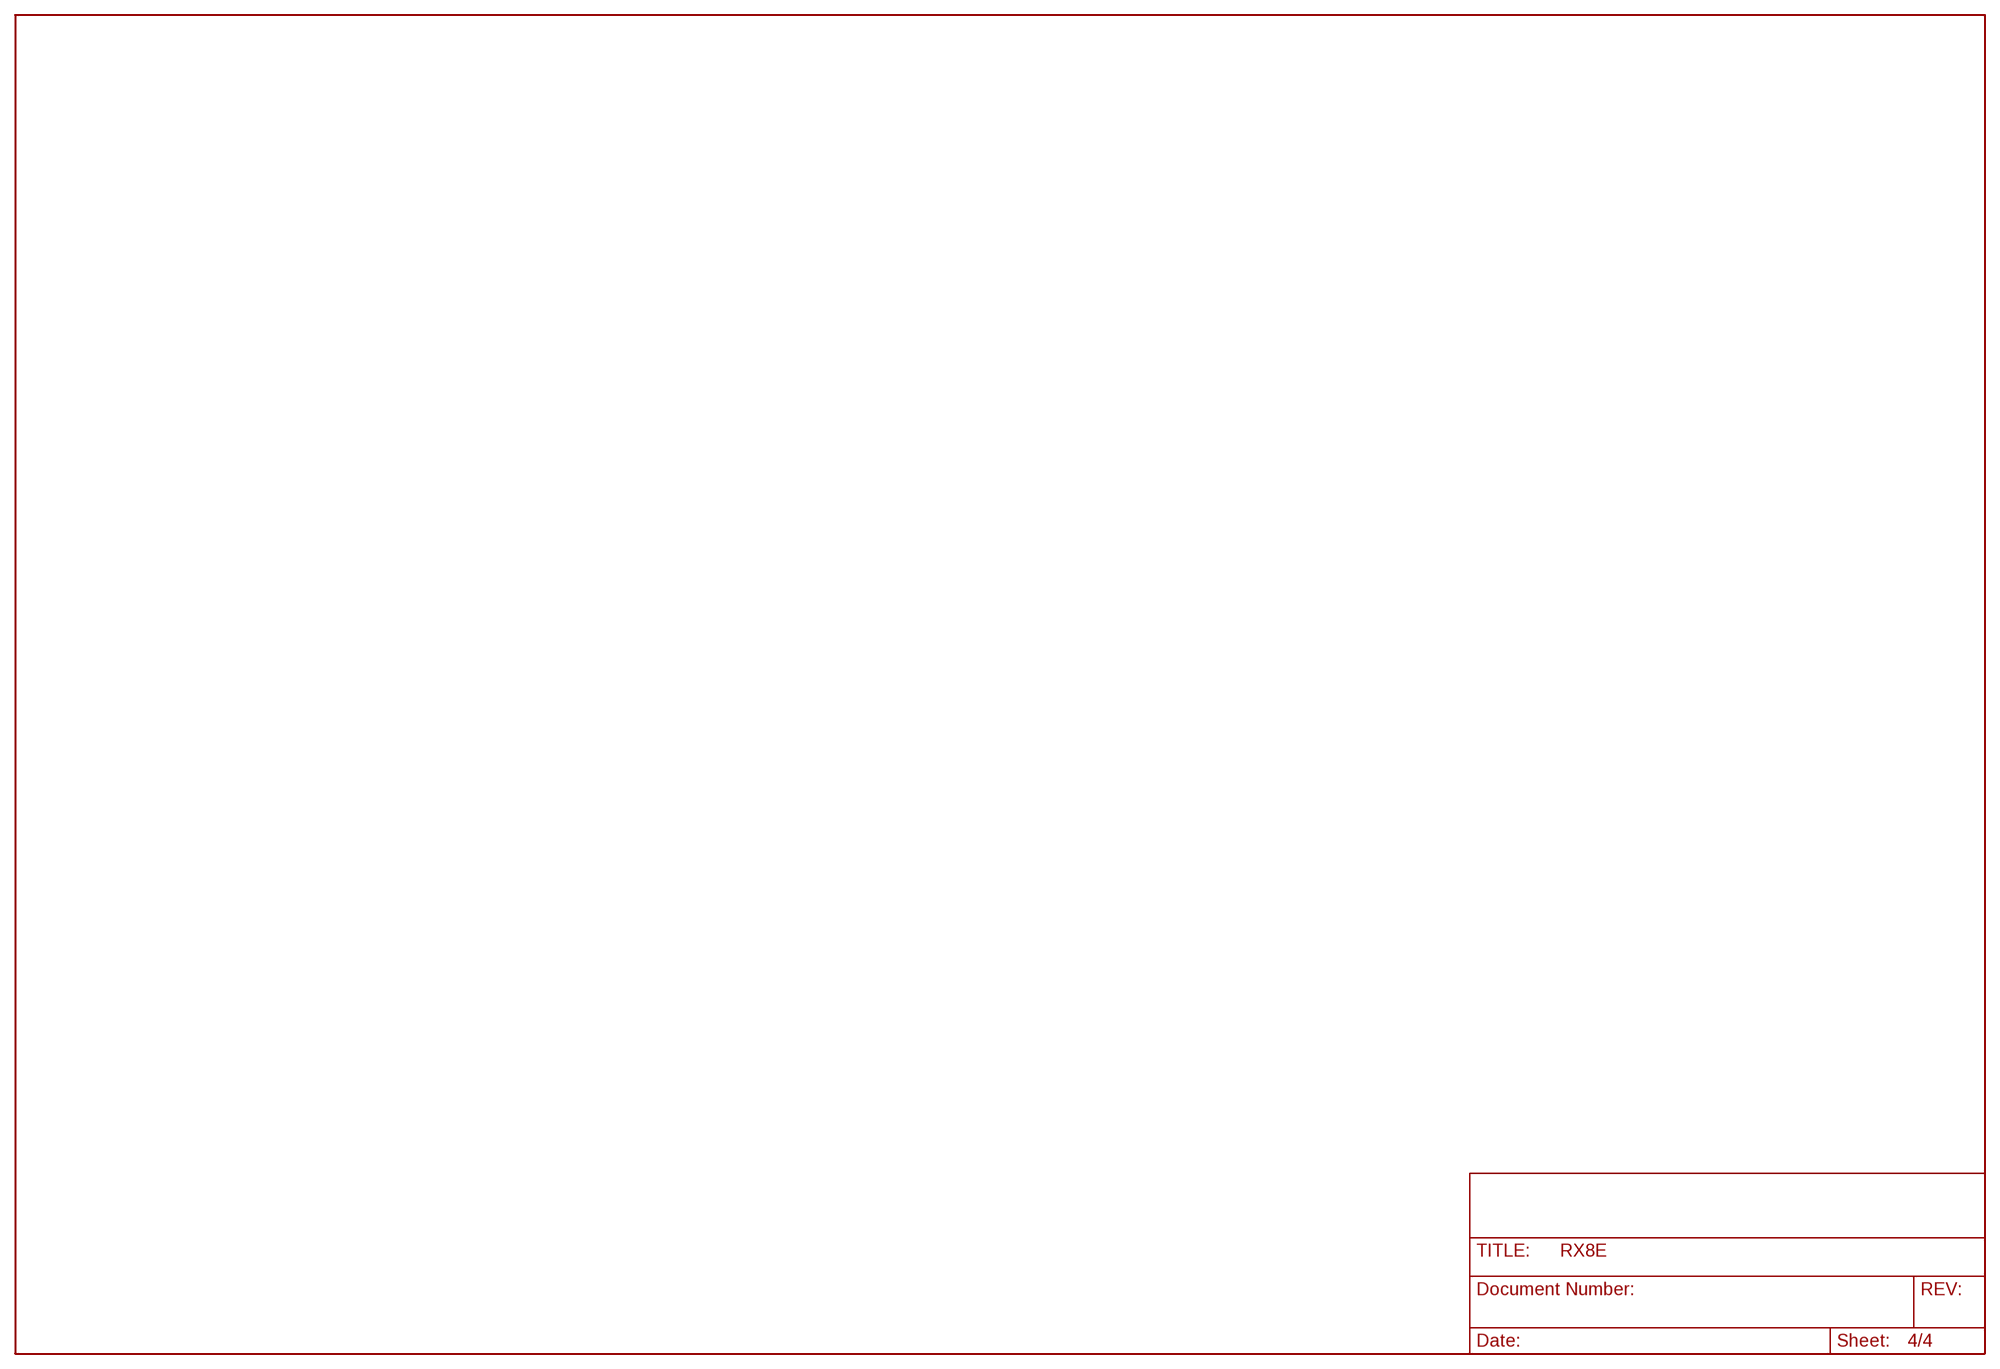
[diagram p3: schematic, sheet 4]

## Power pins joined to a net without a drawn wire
GND: E1.8(P:GND) E2.7(P:GND) E3.7(P:GND) E5.7(P:GND) E6.7(P:GND) E7.7(P:GND) E8.7(P:GND) E9.8(GND) E10.7(P:GND) E11.1(P:GND) E12.7(P:GND) E14.7(P:GND) E15.7(P:GND) E16.7(P:GND) E17.7(P:GND) E18.7(P:GND) E19.7(P:GND) E20.7(P:GND) E21.8(GND) E22.7(P:GND) E23.7(P:GND) E24.7(P:GND) E25.8(P:GND) E26.7(P:GND) E27.13(P:GND) E28.7(P:GND) E29.7(P:GND) E30.7(P:GND) E32.7(P:GND) E33.8(GND) E34.7(P:GND) E35.7(GND) E36.8(P:GND) E37.7(P:GND) E38.7(P:GND) E39.1(GND) E40.8(P:GND) E41.8(GND)
VCC: E1.16(P:VCC) E2.14(P:VCC) E3.14(P:VCC) E5.14(P:VCC) E6.14(P:VCC) E7.14(P:VCC) E8.14(P:VCC) E9.16(VCC) E10.14(P:VCC) E11.8(P:VCC) E12.14(P:VCC) E14.14(P:VCC) E15.14(P:VCC) E16.14(P:VCC) E17.14(P:VCC) E18.14(P:VCC) E19.14(P:VCC) E20.14(P:VCC) E21.16(VCC) E22.14(P:VCC) E23.14(P:VCC) E24.14(P:VCC) E25.16(P:VCC) E26.14(P:VCC) E27.5(P:VCC) E28.14(P:VCC) E29.14(P:VCC) E30.14(P:VCC) E32.14(P:VCC) E33.16(VCC) E34.14(P:VCC) E35.14(VCC) E36.16(P:VCC) E37.14(P:VCC) E38.14(P:VCC) E39.8(VCC) E40.16(P:VCC) E41.16(VCC)

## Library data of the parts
C1-C41 = rcl:C-US: CAPACITOR, American symbol
C42-C45 = rcl:CPOL-US: POLARIZED CAPACITOR, American symbol
DRIVE = dec-con:DEC40PIN: PIN HEADER
E1 E25 E36 E40 = dec-con:8837: Hex inverting LINE RECEIVER
E2 E7 E15 E22 E26 E30 = 74xx-us:74*74: Dual D type positive edge triggered FLIP FLOP, preset and clear
E3 E10 = 74xx-us:74*10: Triple 3-input NAND gate
E4 = 74ttl-din:74*161: Synchrounus 4-bit COUNTER
E5 E14 E17 E18 E29 E37 = 74xx-us:74*01: Quad 2-input NAND gate, open collector
E6 E19 E23 = 74xx-us:74*02: Quad 2-input NOR gate
E8 E32 E38 = 74xx-us:74*04: Hex INVERTER
E9 E21 E33 = 74xx-us:74*179: 4-bit parallel access SHIFT REGISTER
E11 = dec-con:8640: Quad NOR gate
E12 E24 E34 = 74xx-us:74*00: Quad 2-input NAND gate
E13 = ic-package:DIL16: Dual In Line
E16 = 74xx-us:74*08: Quad 2-input AND gate
E20 = 74xx-us:74*27: Triple 3-input NOR gate
E27 = 74xx-us:74*76: Dual J-K FLIP FLOP, preset and clear
E28 = 74xx-us:74*20: Dual 4-input NAND gate
E31 = special:SW_DIP-8: DIP SWITCH
E35 = dec-con:SP314: 7-Input NOR gate
E39 = dec-con:SP384: Quad OR gate
E41 = 74xx-us:74*42: 4-line to 10-line DECODER (1-of-10)
PAD10-PAD17 PAD20-PAD27 = wirepad:1,6/0,8: THROUGH-HOLE PAD
R1-R17 R19 R20 = rcl:R-US_: RESISTOR, American symbol
U$2 = dec-con:QUAD: Quad-Height DEC board
U$5 = dec-con:OUTLINE-*: Board outlines for DEC boards.

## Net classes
1 supply: width 0.762 mm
